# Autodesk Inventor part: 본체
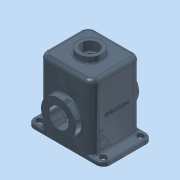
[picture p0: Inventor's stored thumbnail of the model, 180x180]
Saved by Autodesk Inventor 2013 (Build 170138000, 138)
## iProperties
Company: 한국ATC센터
Created: 2014-10
Part Number: 본체
Document SubType Name: Modeling
Designer: 한국ATC센터
Density: 2.71 g/cm^3
Material: 알루미늄 6061
Mass: 3285.46 g
Surface Area: 2358.48 cm^2
Volume: 1212.35 cm^3
Author: KYOUNG IL JANG
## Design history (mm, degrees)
sketch "스케치1"
  geometry: L1 (-70, 65)-(70, 65); L2 (70, 65)-(70, -65); L3 (70, -65)-(-70, -65); L4 (-70, -65)-(-70, 65); 3 further points
  constraints: 8 end point, 2 midpoint, 2 parallel, 1 horizontal, 1 horizontal alignment, 1 perpendicular, 1 vertical alignment
  dimensions: "d0" = 140 distance of L2.end L3.end; "d68" = 130 distance of L3.end L1.start
extrude "돌출1" new body sketch "스케치1" distance "d1" = 180; taper "d2" = 0 deg
fillet "모깎기1" dims "d3" = 20
feature "쉘1" dims "d4" = 10
sketch "스케치2"
  geometry: L1 (-70, 45)-(-70, -45) reference; L2 (-50, -65)-(-82, -65); L3 (-82, 65)-(-50, 65); L4 (-85, 57)-(-82, 57); L5 (-82, 41)-(-85, 41); L6 (-100, 47)-(-100, -47); A1 r 20 centre (-50, 45) between (-50, 65) and (-70, 45) reference; A2 r 20 centre (-50, -45) between (-70, -45) and (-50, -65) reference; A3 r 8 centre (-82, 49) between (-82, 41) and (-82, 57); A4 r 8 centre (-85, 49) between (-85, 57) and (-85, 41); A5 r 18 centre (-82, 47) between (-82, 65) and (-100, 47); A6 r 18 centre (-82, -47) between (-100, -47) and (-82, -65); 1 further point
  constraints: 10 end point, 9 tangent, 8 point on circle, 4 centre point, 2 parallel, 2 perpendicular, 1 equal radius
  dimensions: "d6" = 49 vertical distance of point (0, 0) A3.centre; "d8" = 16 distance between parallel lines of L4 L5; "d64" = 18 radius of A5; "d65" = 12 distance from line of A3.centre L1; "d66" = 30 distance between parallel lines of L6 L1; "d67" = 3 distance of A4.centre A3.centre
extrude "돌출2" join sketch "스케치2" distance "d9" = 10; taper "d10" = 0 deg
extrude "돌출3" cut sketch "스케치2" stored distance "d11" = 10; taper "d12" = 0 deg
sketch "스케치3"
  geometry: L1 (-65, 0)-(-65, 180) reference; L2 (-55, 0)-(-55, 170) reference; L3 (-83, 75)-(-51, 75); L4 (45, 0)-(-45, 0) reference; L5 (-83, 75)-(-83, 120.5); L6 (-83, 120.5)-(-55, 120.5); L7 (-55, 120.5)-(-51, 116.5); L8 (-51, 116.5)-(-51, 75); 2 further points
  constraints: 10 end point, 4 perpendicular, 1 point on line
  dimensions: "d13" = 75 distance between parallel lines of L3 L4; "d14" = 18 distance from line of L1 L3.start; "d15" = 4 distance from line of L3.end L2; "d16" = 91 diameter of L6 L3; "d17" = 135 deg angle of L7 L2
revolve "회전1" sketch "스케치3" stored, may be unused: angle "d18" = 90 deg
sketch "스케치4"
  geometry: C1 r 45.5 at (0, 0) reference; 2 further points
  constraints: 1 vertical alignment
  dimensions: "d19" = 35 distance of C1.centre point (0, 35)
hole "구멍1" sketch "스케치4" at (0, 35) diameter "d20" = 3.459; stored, may be unused: countersink angle "d24" = 90 deg, drill point angle "d26" = 118 deg; dims "d21" = 13, "d22" = 4, "d23" = 2, "d25" = 16
fillet "모깎기2" dims "d30" = 3
hole "구멍2" diameter "d33" = 52; stored, may be unused: countersink angle "d37" = 90 deg, drill point angle "d39" = 118 deg; dims "d31" = 10, "d32" = 10, "d34" = 13, "d35" = 4, "d36" = 2, "d38" = 16
sketch "스케치5"
  geometry: C1 r 31 at (0, 0); 1 further point
  constraints: 1 centre point, 1 coincident
  dimensions: "d40" = 62 diameter of C1
extrude "돌출4" join sketch "스케치5" distance "d41" = 15; taper "d42" = 0 deg
hole "구멍3" diameter "d45" = 43; stored, may be unused: countersink angle "d49" = 90 deg, drill point angle "d51" = 118 deg; dims "d43" = 10, "d44" = 10, "d46" = 13, "d47" = 4, "d48" = 2, "d50" = 16
fillet "모깎기3" dims "d52" = 3
fillet "모깎기4" dims "d53" = 3
chamfer "모따기1" distance "d55" = 1; stored, may be unused: second distance "d56" = 2, angle "d57" = 45 deg
sketch "스케치6"
  geometry: 2 further points
  constraints: 1 vertical alignment, 1 other
  dimensions: "d71" = 90 distance of point (0, 0) point (0, 90)
feature "엠보싱2" sketch "스케치6" dims "d0" = 140, "d68" = 130, "d72" = 1, "d73" = 0
fillet "모깎기6" dims "d74" = 10
sketch "스케치7"
  geometry: C1 r 15 at (0, 0); C2 r 21.5 at (0, 0) reference; C3 r 25 at (0, 0); 1 further point
  constraints: 2 centre point, 2 coincident
  dimensions: "d61" = 30 diameter of C1; "d75" = 50 diameter of C3
extrude "돌출5" join sketch "스케치7" distance "d62" = 10; taper "d63" = 0 deg
feature "면 이동1" dims "d76" = 1
fillet "모깎기7" dims "d77" = 3
node "솔리드1"
mirror "대칭1"
mirror "대칭2"
pattern_circular "원형 패턴1" dims angle "d28" = 360 deg
mirror "대칭3"
